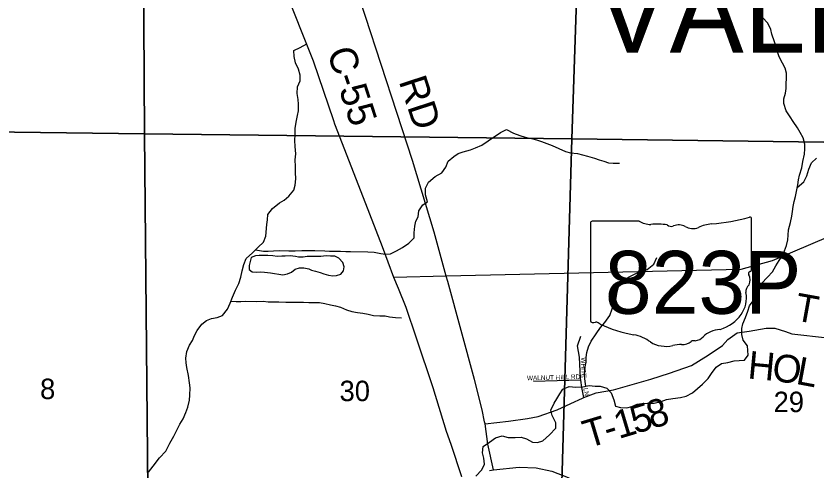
# Model space of a CAD drawing. Extents: x 1624196 to 2029251, y 146837 to 440034.
# Drawn here: x 1822196 to 1830840, y 322951 to 327860 of the extents above; entities that cross this region are included whole.
import ezdxf

# ---------------------------------------------------------------- set-up
doc = ezdxf.new("R2010")
doc.units = 0
for name, color, linetype in [('GM_P_State_Alignment', 7, 'Continuous'), ('GM_P_State_Location', 7, 'Continuous'), ('GM_P_State_Shield', 7, 'Continuous'), ('GM_X_County_Road', 7, 'Continuous'), ('GM_X_County_Road_Text', 7, 'Continuous'), ('GM_X_Minor_Lake', 7, 'Continuous'), ('GM_X_Minor_River', 7, 'Continuous'), ('GM_X_Section', 7, 'Continuous'), ('GM_X_Section_Text', 7, 'Continuous'), ('GM_X_State_Route', 7, 'Continuous'), ('GM_X_Township_Road', 7, 'Continuous'), ('GM_X_Township_Road_Text', 7, 'Continuous'), ('GM_X_Township_Subdivision', 7, 'Continuous'), ('GM_X_Township_Subdivision_Text', 7, 'Continuous'), ('GM_X_Township_Text', 7, 'Continuous'), ('GM_X_US_Route', 7, 'Continuous')]:
    doc.layers.add(name, color=color, linetype=linetype)

msp = doc.modelspace()

# ---------------------------------------------------------------- linework, layer by layer
at = {"layer": 'GM_P_State_Alignment'}
msp.add_lwpolyline([(1841070.6, 322042.9), (1839794.7, 324625.9), (1839247.6, 325350.5), (1838632.2, 326165.4), (1838342.4, 326513.4), (1837975.2, 326880.6), (1837637.1, 327199.5), (1837385.9, 327479.8), (1836999.5, 327644.1), (1836468.1, 327789.1), (1836052.7, 327856.7), (1835538, 327819), (1835028.6, 327760.1), (1834429.6, 327489.5), (1834101.1, 327199.5), (1833589.1, 326735.6), (1832690.6, 326291.1), (1831391.2, 325648.4), (1830367.1, 325213.5), (1830029, 325116.9), (1826845.3, 325045.2), (1826279.7, 325032.4)], dxfattribs=at)
at = {"layer": 'GM_P_State_Shield'}
for p, q in [((1830144.3, 325113.6), (1830144.3, 325666.3)), ((1828404.1, 325621.9), (1828404.1, 324565.3)), ((1828930.9, 325640.1), (1828421.2, 325640.1)), ((1830144.1, 325113.7), (1830144.3, 325113.6))]:
    msp.add_line(p, q, dxfattribs=at)
for centre, major_axis, start_param, end_param in [((1829524.4, 327080.7), (1845.5, 0), 4.814394, 5.042369), ((1830125, 325668.6), (19.4, 0), 6.141152, 7.989035), ((1828424, 325624.2), (20.2, 0), 1.712693, 3.28349), ((1829052.2, 325762.8), (195.5, 0), 4.042523, 4.731795), ((1829117.1, 325046.9), (702, 0), 1.404758, 1.657858), ((1829276.4, 325629.7), (56.4, 0), 3.836095, 5.185415), ((1829359.3, 325507.5), (117.3, 0), 0.950623, 2.079405), ((1829510.6, 325675), (141.1, 0), 4.081561, 5.145723), ((1829759.8, 325317.4), (371.3, 0), 1.699011, 2.107814), ((1830139.8, 325073), (30, 0), 1.883978, 3.671073), ((1829949.1, 325003.1), (180, 0), 5.934695, 6.695948), ((1830123.6, 325111.4), (20.7, 0), 5.05454, 6.418171), ((1830213.7, 324882.2), (130.9, 0), 2.387724, 3.262537), ((1829627.8, 324811.9), (461.6, 0), 5.101752, 6.440018), ((1828424.2, 324563), (20.3, 0), 3.00124, 4.508301), ((1828427.3, 324671.1), (155.2, 0), 4.665946, 4.897461), ((1828459.1, 324504.3), (56, 0), 0.519207, 1.627899), ((1829165.7, 325453.7), (1332.7, 0), 4.195997, 4.488961), ((1829822.4, 324268.7), (252.8, 0), 1.647645, 2.488434), ((1828768.3, 324090.6), (417, 0), 0.823519, 1.323587), ((1829502.1, 324462.9), (149.1, 0), 4.937069, 5.64225), ((1829219.3, 324499.1), (264.6, 0), 4.026481, 4.996735), ((1829372.2, 324133.8), (217.4, 0), 1.495662, 1.94098), ((1829391.5, 324420), (141, 0), 4.691044, 5.507374), ((1829519.1, 324317.6), (39.7, 0), 1.147584, 2.315152)]:
    msp.add_ellipse(centre, major_axis=major_axis, ratio=0.8, start_param=start_param, end_param=end_param, dxfattribs=at)
at = {"layer": 'GM_X_County_Road'}
for points in [[(1827259.8, 323472.2), (1827233.4, 323600.8), (1827150.5, 323930.8), (1826860.9, 324988.7), (1826845.3, 325045.2), (1826713, 325522.1), (1826481.2, 326297.1), (1825804.1, 328375.3), (1825599.3, 329028.7), (1825269.6, 330080.5), (1825198.4, 330242.2), (1824914.5, 330561.3), (1823297.2, 332255.7), (1823166.4, 332392.9), (1823101.4, 332429.2), (1823060.1, 332448.6), (1823019.8, 332458), (1823006.6, 332460.4), (1822990.3, 332461), (1822859.8, 332406.9)], [(1827356.9, 322954.3), (1827293.2, 323229.2), (1827264.1, 323451.3), (1827259.8, 323472.2)]]:
    msp.add_lwpolyline(points, dxfattribs=at)
at = {"layer": 'GM_X_Minor_Lake'}
for points in [[(1825269.6, 325252.8), (1825247.5, 325252.8), (1825215.5, 325258.9), (1825159.4, 325265), (1825103.2, 325263.2), (1825067.2, 325261.2), (1825017, 325257.4), (1824971, 325265.5), (1824916.9, 325271.6), (1824824.7, 325271.8), (1824782.5, 325265.9), (1824738.4, 325250), (1824726.3, 325205.9), (1824716.1, 325161.8), (1824716, 325119.7), (1824748, 325093.6), (1824792.1, 325089.5), (1824838.2, 325093.4), (1824882.3, 325091.3)], [(1824882.3, 325091.3), (1824946.4, 325083.1), (1824988.5, 325077), (1825034.6, 325068.8), (1825080.7, 325062.7), (1825130.8, 325070.6), (1825173, 325090.6), (1825213.1, 325122.6), (1825259.3, 325136.5), (1825307.4, 325138.4), (1825359.5, 325124.2), (1825389.5, 325112.1), (1825431.6, 325100), (1825483.6, 325085.8), (1825523.7, 325071.7), (1825573.8, 325057.6), (1825617.9, 325051.5), (1825657.9, 325053.4), (1825706.1, 325069.3), (1825736.3, 325103.3), (1825740.4, 325147.4), (1825728.5, 325195.6), (1825684.5, 325239.8), (1825642.5, 325263.9), (1825592.3, 325264), (1825552.3, 325268.1), (1825520.2, 325264.2), (1825490.1, 325260.3), (1825446, 325258.4), (1825387.9, 325260.5), (1825341.8, 325258.6), (1825297.7, 325252.7), (1825269.6, 325252.8)]]:
    msp.add_lwpolyline(points, dxfattribs=at)
at = {"layer": 'GM_X_Minor_River'}
for points in [[(1830604.3, 325853.5), (1830618.5, 325909.6), (1830628.7, 325963.7), (1830642.9, 326035.8), (1830651.1, 326087.8), (1830663.2, 326137.9), (1830685.5, 326218), (1830699.7, 326288.1), (1830716, 326364.2), (1830718.1, 326422.3), (1830720.3, 326472.4), (1830700.5, 326542.6), (1830670.6, 326598.8), (1830640.7, 326651), (1830594.9, 326717.3), (1830563, 326767.6), (1830517.1, 326835.9), (1830493.3, 326912.1), (1830491.5, 326964.2), (1830509.7, 327024.3), (1830517.8, 327074.3), (1830518, 327126.5), (1830520.2, 327188.6), (1830520.3, 327242.7), (1830508.5, 327294.8), (1830476.6, 327349), (1830440.8, 327419.3), (1830424.9, 327471.5), (1830411, 327525.6), (1830391.2, 327581.8), (1830363.4, 327662.1), (1830351.5, 327714.2), (1830319.7, 327782.5), (1830263.8, 327842.8), (1830203.9, 327901.2)], [(1825209.8, 326514.1), (1825212.4, 326578.2), (1825212.9, 326642.3), (1825223.5, 326712.4), (1825238.2, 326782.4), (1825248.6, 326832.4), (1825249.3, 326904.6), (1825245.7, 326956.7), (1825234.3, 327023), (1825236.9, 327093.1), (1825267.5, 327159), (1825268, 327219.1), (1825246.6, 327285.4), (1825217.1, 327353.8), (1825199.7, 327420.1), (1825198.3, 327488.2), (1825264.6, 327517.8), (1825337.1, 327557.3)], [(1826189.1, 325283.9), (1826243.2, 325287.7), (1826307.3, 325319.5), (1826373.5, 325355.4), (1826441.7, 325403.2), (1826498, 325461.2), (1826498.2, 325515.3), (1826504.4, 325587.4), (1826516.5, 325639.5), (1826542.7, 325689.5), (1826548.9, 325751.6), (1826593.2, 325819.6), (1826643.3, 325849.5), (1826619.5, 325925.7), (1826619.7, 325997.8), (1826654, 326061.8), (1826724.2, 326123.7), (1826796.5, 326163.5), (1826840.7, 326223.5), (1826864.9, 326289.6), (1826925.1, 326339.5), (1826975.3, 326371.3), (1827027.4, 326391.2), (1827105.6, 326411), (1827159.7, 326432.8), (1827229.9, 326462.6), (1827298.1, 326508.5), (1827430.5, 326600.2), (1827494.7, 326634.1), (1827572.7, 326591.7), (1827640.7, 326567.4), (1827696.7, 326551.2), (1827766.8, 326534.9), (1827818.8, 326520.7), (1827872.8, 326502.5), (1827930.8, 326482.2), (1827988.8, 326460), (1828060.8, 326425.6), (1828132.8, 326393.3), (1828188.8, 326381.1), (1828264.9, 326372.8), (1828316.9, 326358.6), (1828371, 326344.4), (1828447, 326324.1), (1828497, 326305.9), (1828547, 326291.7), (1828597, 326273.5), (1828647.1, 326269.3), (1828715.2, 326269)], [(1823628.7, 322927.4), (1823677.3, 322993.1), (1823746.2, 323080.7), (1823812.9, 323154.3), (1823859.7, 323240.1), (1823900.4, 323316), (1823935, 323381.8), (1823965.6, 323447.7), (1824000.2, 323505.6), (1824030.8, 323573.5), (1824053.3, 323631.4), (1824070, 323705.4), (1824074.5, 323759.5), (1824077.2, 323837.6), (1824071.6, 323891.8), (1824058.3, 323974.1), (1824043.1, 324058.4), (1824033.5, 324108.6), (1824029.9, 324158.7), (1824040.6, 324232.8), (1824069.2, 324300.7), (1824101.7, 324352.5), (1824126.2, 324406.5), (1824154.7, 324458.3), (1824205.3, 324528.1), (1824255.7, 324565.7), (1824308, 324587.3), (1824370.2, 324600.9), (1824426.4, 324622.5), (1824481, 324688.1), (1824511.6, 324754), (1824534.3, 324820), (1824567, 324895.9), (1824603.6, 324965.7), (1824626.2, 325035.7), (1824638.8, 325103.7), (1824657.5, 325173.7), (1824684.1, 325237.6), (1824750.7, 325299.2), (1824813.3, 325360.8), (1824871.8, 325414.5), (1824894.4, 325480.4), (1824907.5, 325604.6), (1824912, 325654.7), (1824918.5, 325712.7), (1824969.1, 325776.5), (1825041.7, 325840), (1825092, 325869.6), (1825142.5, 325913.3), (1825197.1, 325977), (1825213.6, 326029), (1825218.2, 326099.1), (1825214.8, 326167.3), (1825215.3, 326233.4), (1825214, 326303.6), (1825218.5, 326369.7), (1825213.2, 326449.9), (1825209.8, 326514.1)], [(1830637.2, 326006.8), (1830707.1, 326065.6), (1830741.3, 326129.6), (1830763.5, 326201.7), (1830791.8, 326271.7), (1830844, 326321.6)], [(1827165.1, 322885.5), (1827229.4, 322951.4), (1827259.6, 323015.4), (1827251.8, 323079.6), (1827236, 323135.8), (1827242.2, 323205.9), (1827312.4, 323251.7), (1827378.6, 323299.6), (1827448.8, 323321.4), (1827514.8, 323301.1), (1827588.9, 323302.9), (1827655, 323306.6), (1827711, 323286.4), (1827777, 323250.1), (1827831.1, 323249.9), (1827889.2, 323267.7), (1827959.5, 323331.6), (1828029.8, 323401.5), (1828027.9, 323459.6), (1827988.1, 323540), (1827976.3, 323598.1), (1828010.5, 323672.1), (1828038.7, 323722.1), (1828072.9, 323774.1), (1828105.1, 323826.1), (1828173.3, 323854), (1828243.4, 323845.7), (1828319.5, 323849.4), (1828387.6, 323863.2), (1828455.7, 323859), (1828509.7, 323856.8), (1828581.7, 323836.5), (1828625.7, 323786.2), (1828655.5, 323708), (1828673.3, 323639.8), (1828727.3, 323625.5), (1828795.4, 323621.3), (1828851.5, 323639.1), (1828909.6, 323661), (1828959.7, 323670.8), (1829017.8, 323674.6), (1829089.9, 323674.3), (1829166, 323692.1), (1829224.2, 323714), (1829294.3, 323725.7), (1829374.4, 323733.5), (1829436.6, 323749.3), (1829504.8, 323785.1), (1829558.9, 323831), (1829615.2, 323878.9), (1829675.4, 323940.8), (1829709.6, 323992.8), (1829759.9, 324062.8), (1829820.1, 324100.7), (1829888.2, 324112.5), (1829954.3, 324130.2), (1830008.4, 324134.1), (1830066.5, 324137.9), (1830108.7, 324191.8), (1830104.9, 324244), (1830101, 324294.1), (1830053.1, 324356.4), (1830039.3, 324414.5), (1830037.5, 324480.7), (1830049.7, 324532.7), (1830077.9, 324600.8), (1830102.1, 324666.8), (1830122.3, 324726.9), (1830170.6, 324794.9), (1830202.8, 324868.9), (1830231, 324918.9), (1830253.2, 324968.9), (1830317.5, 325034.8), (1830371.7, 325092.8), (1830408, 325158.8), (1830442.2, 325216.8), (1830478.4, 325268.8), (1830500.6, 325320.8), (1830520.8, 325378.8), (1830537, 325438.9), (1830539.1, 325491), (1830543.3, 325549.1), (1830563.6, 325627.2), (1830579.8, 325695.3), (1830586, 325747.4), (1830594.1, 325799.5), (1830604.3, 325853.5)], [(1824784, 325332), (1824869, 325316.3), (1824921, 325317.9), (1824977.1, 325321.4), (1825043.2, 325322.9), (1825145.3, 325322), (1825213.3, 325319.5), (1825283.5, 325322.9), (1825353.5, 325324.3), (1825423.6, 325323.7), (1825531.7, 325318.8), (1825583.7, 325316.4), (1825653.8, 325317.8), (1825703.9, 325317.4), (1825759.9, 325314.9), (1825809.9, 325312.5), (1825998.1, 325311), (1826066.2, 325306.4), (1826138.9, 325291.2), (1826189.1, 325283.9)], [(1828352.6, 323856.1), (1828345.7, 323907.5), (1828339.9, 323973.6), (1828342.1, 324051.8), (1828356.3, 324117.8), (1828356.5, 324168), (1828362.6, 324222), (1828380.8, 324284.1), (1828411, 324344.1), (1828465.4, 324422.1), (1828511.6, 324490.1), (1828559.8, 324544), (1828614.1, 324622), (1828636.4, 324694), (1828654.6, 324756.1), (1828680.8, 324814.1), (1828693, 324882.2), (1828711.2, 324944.3), (1828761.4, 324998.2), (1828815.6, 325036.1), (1828901.8, 325077.9), (1828958, 325099.8), (1829016.1, 325119.6), (1829088.4, 325175.5), (1829120.6, 325249.5)], [(1824519, 324775.6), (1824573.9, 324771.6), (1824625.9, 324773.1), (1824676, 324774.7), (1824798.1, 324773.7), (1824868.2, 324775.1), (1824922.2, 324770.7), (1824974.3, 324770.2), (1825036.3, 324767.7), (1825112.4, 324765.1), (1825174.5, 324764.6), (1825250.6, 324766), (1825302.6, 324765.5), (1825358.6, 324763.1), (1825412.7, 324760.6), (1825476.7, 324760.1), (1825532.7, 324749.6), (1825592.7, 324737.1), (1825648.6, 324726.6), (1825700.6, 324712.1), (1825768.4, 324683.5), (1825826.3, 324665), (1825884.3, 324654.5), (1825942.2, 324646), (1826000.2, 324635.5), (1826058.2, 324621), (1826126.2, 324616.4), (1826185.4, 324616.5)], [(1826185.4, 324616.5), (1826231.1, 324608.3), (1826295.2, 324600.1), (1826361.2, 324595.8)]]:
    msp.add_lwpolyline(points, dxfattribs=at)
at = {"layer": 'GM_X_Section'}
for points in [[(1828392.6, 332222.1), (1828201.1, 326533), (1823585.4, 326583.9), (1823553.1, 332024.2), (1827488.7, 332248.5)], [(1832918.1, 332106.3), (1833100.9, 326465.3), (1828201.1, 326533), (1828392.6, 332222.1)], [(1823585.4, 326583.9), (1828201.1, 326533), (1828042.7, 321077.6), (1823633.9, 321187.6)], [(1833100.9, 326465.3), (1832892.1, 320934.1), (1828042.7, 321077.6), (1828201.1, 326533)]]:
    msp.add_lwpolyline(points, close=True, dxfattribs=at)
for points in [[(1819430, 331863.8), (1823553.1, 332024.2), (1823585.4, 326583.9), (1819931.6, 326632.6)], [(1819931.6, 326632.6), (1823585.4, 326583.9), (1823633.9, 321187.6), (1821202.9, 321686.7)]]:
    msp.add_lwpolyline(points, dxfattribs=at)
at = {"layer": 'GM_X_State_Route'}
msp.add_lwpolyline([(1827314, 322947.2), (1827356.9, 322954.3), (1827633.5, 322979.8), (1827815.5, 322974.4), (1827984.8, 322938), (1828163.1, 322870.6), (1828414, 322717.7), (1828593.2, 322587.3), (1829126.7, 322139.2), (1829391.5, 321898.8), (1829643.1, 321660.6), (1830065.7, 321321.5), (1830199.3, 321226.5), (1830267.3, 321178.7), (1830440.6, 321056.8), (1830570.4, 320989.9), (1830710.1, 320918.9), (1830948.2, 320905.5), (1831116.9, 320899.6)], dxfattribs=at)
at = {"layer": 'GM_X_Township_Road'}
msp.add_lwpolyline([(1827264.1, 323451.3), (1827517, 323479.6), (1827722.8, 323508.9), (1827836.7, 323528.7), (1828043.7, 323602.1), (1828192.8, 323670.6), (1828318, 323728.7), (1828329.8, 323733.3), (1828465.2, 323785.2), (1828651, 323818.2), (1829055.6, 323932.8), (1829258.8, 323998.2), (1829495.7, 324082.1), (1829674.1, 324193.2), (1829828.6, 324297.9), (1829887.6, 324361), (1829988.6, 324434.7), (1830118.5, 324450.8), (1830302.2, 324483.8), (1830396.3, 324485.2), (1830511, 324449), (1830579.5, 324424), (1830675.9, 324411.5), (1831057.1, 324369.3)], dxfattribs=at)
at = {"layer": 'GM_X_Township_Subdivision'}
for points in [[(1828311.1, 323844.2), (1828298.2, 323920.5), (1828294.4, 323942.9), (1828284.7, 324169.3), (1828262.6, 324293.3), (1828300.9, 324396.1)], [(1828298.2, 323920.5), (1827788.3, 323906.9)], [(1828329.8, 323733.3), (1828311.2, 323843.6), (1828311.1, 323844.2)]]:
    msp.add_lwpolyline(points, dxfattribs=at)
at = {"layer": 'GM_X_US_Route'}
for points in [[(1825641.9, 326691.6), (1825628.6, 326725.9), (1825409.8, 327372.7), (1825088.1, 328177.2), (1824868, 328679.6), (1824642.2, 329091.7), (1824305.4, 329741.3), (1823817.2, 330704.9), (1823233.4, 331748.4), (1822859.8, 332406.9), (1822857, 332412), (1822727.8, 332699), (1822213.7, 333688.8), (1822097.2, 333916.9), (1822016.9, 334050.8)], [(1826896.2, 323225.8), (1826848.8, 323367.8), (1826703.4, 323840.1), (1826522.2, 324376.5), (1826412.5, 324707.7), (1826329.8, 324911.7), (1826279.7, 325032.4), (1826155, 325363), (1825951.9, 325892.2), (1825641.9, 326691.6)], [(1827012.9, 322876.1), (1827012.9, 322876.1), (1826896.2, 323225.8)]]:
    msp.add_lwpolyline(points, dxfattribs=at)

# ---------------------------------------------------------------- texts
at = {"layer": 'GM_P_State_Location'}
msp.add_text('823P', height=1, rotation=0.00001, dxfattribs=at).set_placement((1828831.2, 324977.9))
for s in ['s', 'r']:
    msp.add_text(s, height=1, dxfattribs=at).set_placement((1829254.6, 325023.4))
at = {"layer": 'GM_P_State_Shield'}
msp.add_text('823P', height=680, dxfattribs=at).set_placement((1828558.5, 324639.8))
at = {"layer": 'GM_X_County_Road_Text'}
for s, rotation, p in [('C-55', 287.78342, (1825554.1, 327473.9)), ('RD', 288.12144, (1826329.9, 327155))]:
    msp.add_text(s, height=300, rotation=rotation, dxfattribs=at).set_placement(p)
at = {"layer": 'GM_X_Section_Text'}
for s, p in [('8', (1822455.6, 323717.4)), ('30', (1825691.8, 323695.4)), ('29', (1830382.2, 323576.7))]:
    msp.add_text(s, height=221, rotation=0.00001, dxfattribs=at).set_placement(p)
at = {"layer": 'GM_X_Township_Road_Text'}
for s, rotation, p in [('T', 349.68021, (1830594.7, 324572.5)), ('H', 354.63738, (1830095, 323941.6)), ('O', 352.55147, (1830355, 323917.3)), ('L', 349.42721, (1830612.5, 323883.7)), ('5', 16.82746, (1828886.2, 323338.4)), ('8', 17.01412, (1829064.1, 323392.2)), ('1', 16.73598, (1828708.7, 323285)), ('T', 16.69185, (1828375.5, 323185.1)), ('-', 16.69281, (1828590.5, 323249.6))]:
    msp.add_text(s, height=300, rotation=rotation, dxfattribs=at).set_placement(p)
at = {"layer": 'GM_X_Township_Subdivision_Text'}
for s, rotation, p in [('WHITE', 272.54837, (1828299.4, 324166.3)), ('WALNUT HILL RD', 1.45741, (1827717.8, 323920.1)), ('LN', 281.89272, (1828325.6, 323833.5))]:
    msp.add_text(s, height=50, rotation=rotation, dxfattribs=at).set_placement(p)
at = {"layer": 'GM_X_Township_Text'}
msp.add_text('VALLEY', height=900, rotation=0.00001, dxfattribs=at).set_placement((1828454.8, 327461.7))

doc.saveas('drawing.dxf')
